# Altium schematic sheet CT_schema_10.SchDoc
size 278 x 170 mm
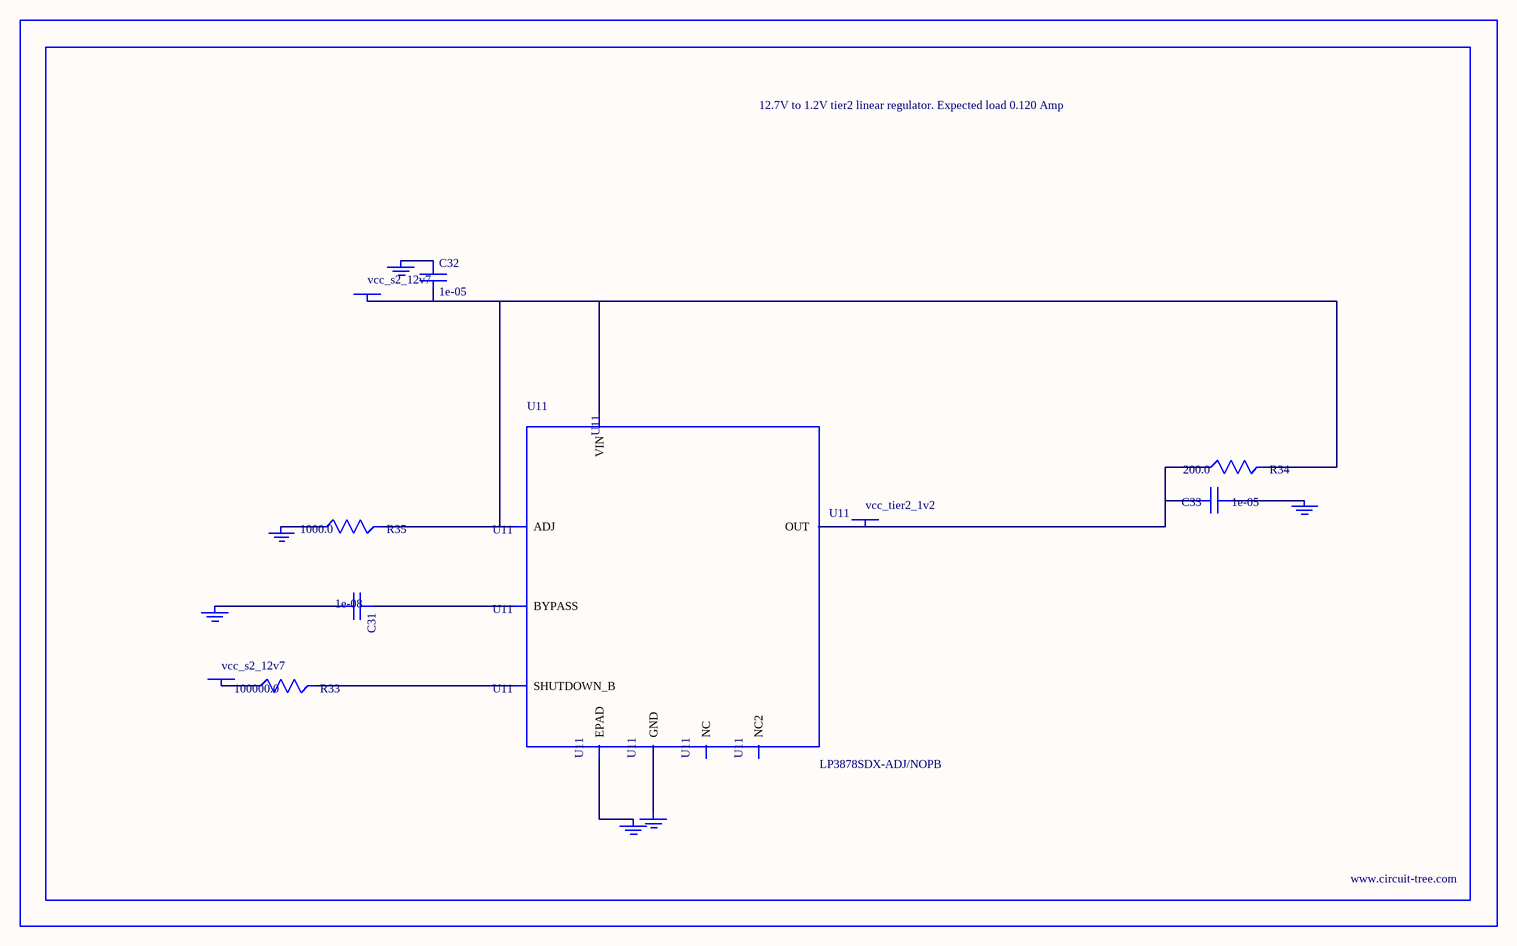
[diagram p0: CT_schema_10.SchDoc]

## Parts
BORDER9  (no value)
C31  1e-08  [C0402]
C32  1e-05  [C1210]
C33  1e-05  [C0805]
GND_INSTANCE_9_0  (no value)
GND_INSTANCE_9_1  (no value)
GND_INSTANCE_9_2  (no value)
GND_INSTANCE_9_3  (no value)
GND_INSTANCE_9_4  (no value)
GND_INSTANCE_9_5  (no value)
POWER_INSTANCE_9_0  vcc_s2_12v7
POWER_INSTANCE_9_1  vcc_s2_12v7
POWER_INSTANCE_9_2  vcc_tier2_1v2
R33  100000.0  [R0603]
R34  200.0  [R0603]
R35  1000.0  [R0603]
U11  LP3878SDX-ADJ/NOPB  [WSON-8]

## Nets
NetC31_1: C31.1 U11.1(BYPASS)
NetC31_2: C31.2 GND_INSTANCE_9_0.0(GND)
NetC32_1: C32.1 GND_INSTANCE_9_1.0(GND)
NetC32_2: C32.2 POWER_INSTANCE_9_0.0(PWR) R34.2 R35.2 U11.4(VIN) U11.6(ADJ)
NetC33_1: C33.1 GND_INSTANCE_9_2.0(GND)
NetC33_2: C33.2 POWER_INSTANCE_9_2.0(PWR) R34.1 U11.5(OUT)
NetGND_INSTANCE_9_3_0: GND_INSTANCE_9_3.0(GND) R35.1
NetGND_INSTANCE_9_4_0: GND_INSTANCE_9_4.0(GND) U11.PAD(EPAD)
NetGND_INSTANCE_9_5_0: GND_INSTANCE_9_5.0(GND) U11.3(GND)
NetPOWER_INSTANCE_9_1_0: POWER_INSTANCE_9_1.0(PWR) R33.1
NetR33_2: R33.2 U11.8(SHUTDOWN_B)

Not connected (* = marked no-connect by the designer): U11 2(NC) 7(NC2)

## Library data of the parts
BORDER9 = BORDER_PAGE9
C31 = C0402C103K3RAC
C32 = C1210C106K5PACTU
C33 = GRM219R60J106ME19D
GND_INSTANCE_9_0-GND_INSTANCE_9_5 = GND
POWER_INSTANCE_9_0-POWER_INSTANCE_9_2 = PWR
R33 = RC0603JR-07100KL
R34 = RC0603JR-07200RL
R35 = RC0603JR-071KL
